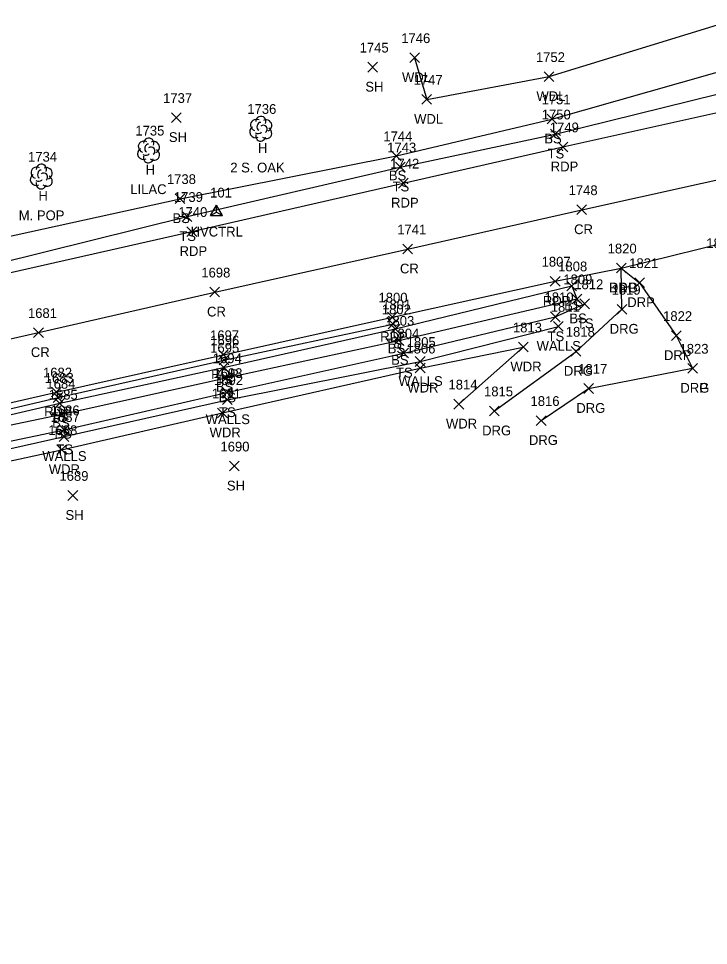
# Model space of a CAD drawing. Extents: x 1611797 to 1633212, y 298978 to 305475.
# Drawn here: x 1613578.2 to 1613719.6, y 301197.3 to 301387.3 of the extents above; entities that cross this region are included whole.
import ezdxf

# ---------------------------------------------------------------- set-up
doc = ezdxf.new("R2010")
doc.units = 0
for name, color, linetype in [('C_A', 7, 'Continuous'), ('C_I', 7, 'Continuous'), ('CPSM', 7, 'Continuous'), ('L_A', 7, 'Continuous'), ('L_C', 7, 'Continuous'), ('L_I', 7, 'Continuous'), ('L_TIC', 7, 'Continuous'), ('LAWA', 7, 'Continuous'), ('LELB', 7, 'Continuous'), ('LTD', 7, 'Continuous'), ('LWS', 7, 'Continuous'), ('P_A', 7, 'Continuous'), ('P_I', 7, 'Continuous'), ('P_TIC', 7, 'Continuous'), ('PET', 7, 'Continuous'), ('PRC', 7, 'Continuous'), ('R_A', 7, 'Continuous'), ('R_I', 7, 'Continuous'), ('R_TIC', 7, 'Continuous'), ('RDG', 7, 'Continuous'), ('RDP', 7, 'Continuous')]:
    doc.layers.add(name, color=color, linetype=linetype)

msp = doc.modelspace()

# ---------------------------------------------------------------- linework, layer by layer
at = {"layer": 'CPSM'}
for p, q in [((1613617.56, 301346.93), (1613618.81, 301349.09)), ((1613617.56, 301346.93), (1613618.81, 301347.65)), ((1613620.06, 301346.93), (1613618.81, 301349.09)), ((1613618.81, 301347.65), (1613618.81, 301349.09)), ((1613618.81, 301347.65), (1613618.81, 301347.65)), ((1613618.81, 301347.65), (1613620.06, 301346.93)), ((1613617.56, 301346.93), (1613620.06, 301346.93))]:
    msp.add_line(p, q, dxfattribs=at)
at = {"layer": 'L_TIC'}
for points in [[(1613658.39, 301378.3), (1613660.39, 301380.3)], [(1613660.39, 301378.3), (1613658.39, 301380.3)], [(1613649.81, 301376.36), (1613651.81, 301378.36)], [(1613651.81, 301376.36), (1613649.81, 301378.36)], [(1613685.93, 301374.42), (1613687.93, 301376.42)], [(1613687.93, 301374.42), (1613685.93, 301376.42)], [(1613660.87, 301369.75), (1613662.87, 301371.75)], [(1613662.87, 301369.75), (1613660.87, 301371.75)], [(1613609.55, 301366.03), (1613611.55, 301368.03)], [(1613611.55, 301366.03), (1613609.55, 301368.03)], [(1613686.53, 301365.74), (1613688.53, 301367.74)], [(1613688.53, 301365.74), (1613686.53, 301367.74)], [(1613687.22, 301362.65), (1613689.22, 301364.65)], [(1613689.22, 301362.65), (1613687.22, 301364.65)], [(1613654.67, 301358.18), (1613656.67, 301360.18)], [(1613656.67, 301358.18), (1613654.67, 301360.18)], [(1613655.46, 301355.9), (1613657.46, 301357.9)], [(1613657.46, 301355.9), (1613655.46, 301357.9)], [(1613610.33, 301349.41), (1613612.33, 301351.41)], [(1613612.33, 301349.41), (1613610.33, 301351.41)], [(1613611.77, 301345.75), (1613613.77, 301347.75)], [(1613613.77, 301345.75), (1613611.77, 301347.75)], [(1613690.58, 301331.52), (1613692.58, 301333.52)], [(1613692.58, 301331.52), (1613690.58, 301333.52)], [(1613691.65, 301328.87), (1613693.65, 301330.87)], [(1613693.65, 301328.87), (1613691.65, 301330.87)], [(1613691.65, 301328.87), (1613693.65, 301330.87)], [(1613693.65, 301328.87), (1613691.65, 301330.87)], [(1613693.23, 301327.86), (1613695.23, 301329.86)], [(1613695.23, 301327.86), (1613693.23, 301329.86)], [(1613687.21, 301325.19), (1613689.21, 301327.19)], [(1613689.21, 301325.19), (1613687.21, 301327.19)], [(1613653.96, 301323.72), (1613655.96, 301325.72)], [(1613655.96, 301323.72), (1613653.96, 301325.72)], [(1613687.84, 301323.24), (1613689.84, 301325.24)], [(1613689.84, 301323.24), (1613687.84, 301325.24)], [(1613654.44, 301322.72), (1613656.44, 301324.72)], [(1613656.44, 301322.72), (1613654.44, 301324.72)], [(1613655.14, 301320.37), (1613657.14, 301322.37)], [(1613657.14, 301320.37), (1613655.14, 301322.37)], [(1613656.17, 301317.76), (1613658.17, 301319.76)], [(1613658.17, 301317.76), (1613656.17, 301319.76)], [(1613680.66, 301319), (1613682.66, 301321)], [(1613682.66, 301319), (1613680.66, 301321)], [(1613619.32, 301316.34), (1613621.32, 301318.34)], [(1613621.32, 301316.34), (1613619.32, 301318.34)], [(1613659.53, 301316.03), (1613661.53, 301318.03)], [(1613661.53, 301316.03), (1613659.53, 301318.03)], [(1613619.25, 301314.84), (1613621.25, 301316.84)], [(1613621.25, 301314.84), (1613619.25, 301316.84)], [(1613659.53, 301314.68), (1613661.53, 301316.68)], [(1613661.53, 301314.68), (1613659.53, 301316.68)], [(1613619.79, 301312.69), (1613621.79, 301314.69)], [(1613621.79, 301312.69), (1613619.79, 301314.69)], [(1613619.91, 301309.65), (1613621.91, 301311.65)], [(1613621.91, 301309.65), (1613619.91, 301311.65)], [(1613585.35, 301308.65), (1613587.35, 301310.65)], [(1613587.35, 301308.65), (1613585.35, 301310.65)], [(1613620.04, 301308.2), (1613622.04, 301310.2)], [(1613622.04, 301308.2), (1613620.04, 301310.2)], [(1613585.69, 301307.47), (1613587.69, 301309.47)], [(1613587.69, 301307.47), (1613585.69, 301309.47)], [(1613667.45, 301307.3), (1613669.45, 301309.3)], [(1613669.45, 301307.3), (1613667.45, 301309.3)], [(1613586.16, 301305.24), (1613588.16, 301307.24)], [(1613588.16, 301305.24), (1613586.16, 301307.24)], [(1613619.03, 301305.5), (1613621.03, 301307.5)], [(1613621.03, 301305.5), (1613619.03, 301307.5)], [(1613586.6, 301302.03), (1613588.6, 301304.03)], [(1613588.6, 301302.03), (1613586.6, 301304.03)], [(1613586.58, 301300.66), (1613588.58, 301302.66)], [(1613588.58, 301300.66), (1613586.58, 301302.66)], [(1613586.08, 301297.95), (1613588.08, 301299.95)], [(1613588.08, 301297.95), (1613586.08, 301299.95)], [(1613621.44, 301294.6), (1613623.44, 301296.6)], [(1613623.44, 301294.6), (1613621.44, 301296.6)], [(1613588.37, 301288.58), (1613590.37, 301290.58)], [(1613590.37, 301288.58), (1613588.37, 301290.58)]]:
    msp.add_lwpolyline(points, dxfattribs=at)
at = {"layer": 'LAWA'}
for points in [[(1613659.39, 301379.3), (1613661.87, 301370.75), (1613686.93, 301375.42), (1613730.09, 301388.72), (1613768.03, 301396.97), (1613816.59, 301404.76), (1613861.02, 301415.83), (1613901.25, 301427.67), (1613950.68, 301436.07), (1613982.7, 301436.25), (1614021.38, 301440.86), (1614060.15, 301445.11), (1614098.09, 301453.38), (1614139.15, 301456.54), (1614173, 301459.52), (1614211.23, 301469.75), (1614243.82, 301473.03), (1614282.31, 301479.54), (1614304.52, 301484.61), (1614323.47, 301484.21), (1614343.41, 301488.74), (1614366.06, 301492.98), (1614391.26, 301497.25)], [(1613542.6, 301289.32), (1613587.08, 301298.95), (1613620.03, 301306.5), (1613660.53, 301315.68), (1613681.66, 301320), (1613668.45, 301308.3)]]:
    msp.add_lwpolyline(points, dxfattribs=at)
at = {"layer": 'LELB'}
for points in [[(1613547.64, 301352.14), (1613554.94, 301342.11), (1613572.12, 301341.76), (1613611.33, 301350.41), (1613655.67, 301359.18), (1613687.53, 301366.74), (1613727.39, 301378.05)], [(1613542.94, 301350.02), (1613549.03, 301339.17), (1613554.76, 301335.6), (1613573.69, 301337.05), (1613612.77, 301346.75), (1613656.46, 301356.9), (1613688.22, 301363.65), (1613727.18, 301373.26)], [(1613463.01, 301262.21), (1613459.37, 301279.97), (1613500.95, 301288.36), (1613538.8, 301297.39), (1613586.69, 301308.47), (1613620.25, 301315.84), (1613655.44, 301323.72), (1613691.58, 301332.52), (1613692.65, 301329.87)], [(1613465.06, 301263.06), (1613463.24, 301277.32), (1613501.35, 301286.48), (1613539.01, 301296.17), (1613587.16, 301306.24), (1613620.79, 301313.69), (1613656.14, 301321.37), (1613692.65, 301329.87)], [(1613538.55, 301292.76), (1613587.6, 301303.03), (1613620.91, 301310.65), (1613657.17, 301318.76), (1613688.21, 301326.19), (1613694.23, 301328.86)], [(1613461.59, 301261.05), (1613458.2, 301280.99), (1613461.48, 301280.97), (1613500.66, 301290.09), (1613538.75, 301298.42), (1613586.35, 301309.65), (1613620.32, 301317.34), (1613654.96, 301324.72)]]:
    msp.add_lwpolyline(points, dxfattribs=at)
at = {"layer": 'LTD'}
for p, q in [((1613627.86, 301364.79), (1613627.86, 301364.79)), ((1613627.86, 301364.79), (1613627.86, 301364.79)), ((1613604.86, 301360.35), (1613604.86, 301360.35)), ((1613604.86, 301360.35), (1613604.86, 301360.35)), ((1613582.88, 301355), (1613582.88, 301355)), ((1613582.88, 301355), (1613582.88, 301355))]:
    msp.add_line(p, q, dxfattribs=at)
for centre in [(1613627.9, 301366.23), (1613604.91, 301361.78), (1613582.93, 301356.44)]:
    msp.add_arc(centre, 1.05, 335.5272, 180.9563, dxfattribs=at)
for centre, major_axis, ratio, start_param, end_param in [((1613627.06, 301365.46), (1.21, -0.51), 0.895232, 1.570796, 4.712389), ((1613628.9, 301365.38), (-1.14, -0.48), 0.949671, 1.570796, 4.712389), ((1613626.77, 301364.08), (0.58, -1.04), 0.959034, 3.141593, 6.283185), ((1613627.65, 301365.25), (-0.208, -0.792), 0.645439, 3.141593, 6.283185), ((1613628.36, 301364.63), (-0.5, 0.667), 0.989748, 3.141593, 6.283185), ((1613628.86, 301363.96), (-1.09, 0.79), 0.841452, 1.570796, 4.712389), ((1613627.86, 301363.29), (0.26, 1.06), 0.942809, 1.570796, 4.712389), ((1613627.4, 301364.04), (-0.625, -0.083), 0.423636, 0, 3.141593), ((1613604.07, 301361.01), (1.21, -0.51), 0.895232, 1.570796, 4.712389), ((1613604.65, 301360.8), (-0.208, -0.792), 0.645439, 3.141593, 6.283185), ((1613605.36, 301360.18), (-0.5, 0.667), 0.989748, 3.141593, 6.283185), ((1613605.9, 301360.93), (-1.14, -0.48), 0.949671, 1.570796, 4.712389), ((1613603.78, 301359.64), (0.58, -1.04), 0.959034, 3.141593, 6.283185), ((1613604.86, 301358.85), (0.26, 1.06), 0.942809, 1.570796, 4.712389), ((1613604.4, 301359.6), (-0.625, -0.083), 0.423636, 0, 3.141593), ((1613605.86, 301359.51), (-1.09, 0.79), 0.841452, 1.570796, 4.712389), ((1613581.8, 301354.3), (0.58, -1.04), 0.959034, 3.141593, 6.283185), ((1613582.09, 301355.67), (1.21, -0.51), 0.895232, 1.570796, 4.712389), ((1613582.68, 301355.46), (-0.208, -0.792), 0.645439, 3.141593, 6.283185), ((1613583.38, 301354.84), (-0.5, 0.667), 0.989748, 3.141593, 6.283185), ((1613583.93, 301355.59), (-1.14, -0.48), 0.949671, 1.570796, 4.712389), ((1613582.88, 301353.5), (0.26, 1.06), 0.942809, 1.570796, 4.712389), ((1613582.43, 301354.25), (-0.625, -0.083), 0.423636, 0, 3.141593), ((1613583.88, 301354.17), (-1.09, 0.79), 0.841452, 1.570796, 4.712389)]:
    msp.add_ellipse(centre, major_axis=major_axis, ratio=ratio, start_param=start_param, end_param=end_param, dxfattribs=at)
at = {"layer": 'LWS'}
msp.add_lwpolyline([(1613464.97, 301272.29), (1613505.88, 301281.77), (1613538.96, 301290.74), (1613587.58, 301301.66), (1613621.04, 301309.2), (1613660.53, 301317.03), (1613688.84, 301324.24)], dxfattribs=at)
at = {"layer": 'P_TIC'}
for points in [[(1613688.79, 301360.01), (1613690.79, 301362.01)], [(1613690.79, 301360.01), (1613688.79, 301362.01)], [(1613656.08, 301352.59), (1613658.08, 301354.59)], [(1613658.08, 301352.59), (1613656.08, 301354.59)], [(1613692.64, 301347.14), (1613694.64, 301349.14)], [(1613694.64, 301347.14), (1613692.64, 301349.14)], [(1613612.75, 301342.67), (1613614.75, 301344.67)], [(1613614.75, 301342.67), (1613612.75, 301344.67)], [(1613656.96, 301339.09), (1613658.96, 301341.09)], [(1613658.96, 301339.09), (1613656.96, 301341.09)], [(1613700.72, 301335.19), (1613702.72, 301337.19)], [(1613702.72, 301335.19), (1613700.72, 301337.19)], [(1613687.18, 301332.49), (1613689.18, 301334.49)], [(1613689.18, 301332.49), (1613687.18, 301334.49)], [(1613617.43, 301330.26), (1613619.43, 301332.26)], [(1613619.43, 301330.26), (1613617.43, 301332.26)], [(1613653.85, 301325.13), (1613655.85, 301327.13)], [(1613655.85, 301325.13), (1613653.85, 301327.13)], [(1613581.34, 301321.95), (1613583.34, 301323.95)], [(1613583.34, 301321.95), (1613581.34, 301323.95)], [(1613619.22, 301317.42), (1613621.22, 301319.42)], [(1613621.22, 301317.42), (1613619.22, 301319.42)], [(1613585, 301309.77), (1613587, 301311.77)], [(1613587, 301309.77), (1613585, 301311.77)]]:
    msp.add_lwpolyline(points, dxfattribs=at)
at = {"layer": 'PET'}
for points in [[(1613121.41, 301224.79), (1613160.56, 301237.68), (1613191.83, 301246.9), (1613232.03, 301257.4), (1613266.78, 301265.99), (1613307.07, 301275.59), (1613345.71, 301284.52), (1613390.57, 301294.41), (1613429.34, 301303.04), (1613467.51, 301311.15), (1613505.79, 301320.12), (1613518.1, 301323.19), (1613528.91, 301326.43), (1613552.82, 301331.16), (1613574.84, 301334.87), (1613613.75, 301343.67), (1613657.08, 301353.59), (1613689.79, 301361.01), (1613727.87, 301369.49)], [(1613125.52, 301197.34), (1613165.46, 301210.56), (1613197.64, 301220.33), (1613235.96, 301230.65), (1613275.93, 301240.9), (1613310.52, 301248.77), (1613348.15, 301257.49), (1613383.51, 301265), (1613415.7, 301272.42), (1613432.15, 301275.92), (1613434.22, 301275.29), (1613458.2, 301280.99), (1613500.19, 301291.63), (1613538.86, 301299.99), (1613586, 301310.77), (1613620.22, 301318.42), (1613654.85, 301326.13), (1613688.18, 301333.49), (1613701.72, 301336.19), (1613728.29, 301342.74)]]:
    msp.add_lwpolyline(points, dxfattribs=at)
at = {"layer": 'PRC'}
msp.add_lwpolyline([(1613120.36, 301208.99), (1613162.25, 301223.48), (1613195.66, 301233.48), (1613234.87, 301243.9), (1613270.14, 301252.64), (1613310.48, 301262.07), (1613348.55, 301270.95), (1613393.4, 301280.86), (1613432.68, 301289.65), (1613457.43, 301294.66), (1613497.12, 301303.83), (1613537.55, 301312.86), (1613582.34, 301322.95), (1613618.43, 301331.26), (1613657.96, 301340.09), (1613693.64, 301348.14), (1613730.35, 301356.23)], dxfattribs=at)
at = {"layer": 'R_TIC'}
for points in [[(1613700.72, 301335.19), (1613702.72, 301337.19)], [(1613702.72, 301335.19), (1613700.72, 301337.19)], [(1613700.72, 301335.19), (1613702.72, 301337.19)], [(1613702.72, 301335.19), (1613700.72, 301337.19)], [(1613704.48, 301332.19), (1613706.48, 301334.19)], [(1613706.48, 301332.19), (1613704.48, 301334.19)], [(1613700.87, 301326.74), (1613702.87, 301328.74)], [(1613702.87, 301326.74), (1613700.87, 301328.74)], [(1613712, 301321.34), (1613714, 301323.34)], [(1613714, 301321.34), (1613712, 301323.34)], [(1613691.48, 301318.12), (1613693.48, 301320.12)], [(1613693.48, 301318.12), (1613691.48, 301320.12)], [(1613715.35, 301314.64), (1613717.35, 301316.64)], [(1613717.35, 301314.64), (1613715.35, 301316.64)], [(1613715.35, 301314.64), (1613717.35, 301316.64)], [(1613717.35, 301314.64), (1613715.35, 301316.64)], [(1613694.03, 301310.51), (1613696.03, 301312.51)], [(1613696.03, 301310.51), (1613694.03, 301312.51)], [(1613674.74, 301305.9), (1613676.74, 301307.9)], [(1613676.74, 301305.9), (1613674.74, 301307.9)], [(1613684.32, 301303.93), (1613686.32, 301305.93)], [(1613686.32, 301303.93), (1613684.32, 301305.93)]]:
    msp.add_lwpolyline(points, dxfattribs=at)
at = {"layer": 'RDG'}
for points in [[(1613675.74, 301306.9), (1613692.48, 301319.12), (1613701.87, 301327.74), (1613701.72, 301336.19)], [(1613685.32, 301304.93), (1613695.03, 301311.51), (1613716.35, 301315.64)]]:
    msp.add_lwpolyline(points, dxfattribs=at)
at = {"layer": 'RDP'}
msp.add_lwpolyline([(1613701.72, 301336.19), (1613705.48, 301333.19), (1613713, 301322.34), (1613716.35, 301315.64)], dxfattribs=at)

# ---------------------------------------------------------------- texts
at = {"layer": 'C_A'}
msp.add_text('HVCTRL', height=2, dxfattribs=at).set_placement((1613613.5, 301342.65))
at = {"layer": 'C_I'}
msp.add_text('101', height=2, dxfattribs=at).set_placement((1613617.5, 301350.65))
at = {"layer": 'L_A'}
for s, p in [('WDL', (1613656.81, 301374.3)), ('SH', (1613649.3, 301372.36)), ('WDL', (1613684.35, 301370.42)), ('WDL', (1613659.29, 301365.75)), ('SH', (1613609.04, 301362.03)), ('BS', (1613685.97, 301361.74)), ('H', (1613627.29, 301359.79)), ('TS', (1613686.63, 301358.65)), ('H', (1613604.29, 301355.35)), ('BS', (1613654.11, 301354.18)), ('TS', (1613654.87, 301351.9)), ('H', (1613582.32, 301350)), ('BS', (1613609.78, 301345.41)), ('TS', (1613611.18, 301341.75)), ('BS', (1613690.02, 301327.52)), ('BS', (1613691.09, 301324.87)), ('BS', (1613691.09, 301324.87)), ('TS', (1613692.64, 301323.86)), ('TS', (1613686.62, 301321.19)), ('TS', (1613653.37, 301319.72)), ('WALLS', (1613684.39, 301319.24)), ('BS', (1613653.89, 301318.72)), ('BS', (1613654.58, 301316.37)), ('TS', (1613655.58, 301313.76)), ('WDR', (1613679.02, 301315)), ('TS', (1613618.73, 301312.34)), ('WALLS', (1613656.08, 301312.03)), ('BS', (1613618.69, 301310.84)), ('WDR', (1613657.9, 301310.68)), ('BS', (1613619.23, 301308.69)), ('TS', (1613584.76, 301304.65)), ('WALLS', (1613616.59, 301304.2)), ('TS', (1613619.32, 301305.65)), ('BS', (1613585.14, 301303.47)), ('WDR', (1613665.82, 301303.3)), ('BS', (1613585.6, 301301.24)), ('WDR', (1613617.39, 301301.5)), ('WALLS', (1613583.12, 301296.66)), ('TS', (1613586.01, 301298.03)), ('WDR', (1613584.44, 301293.95)), ('SH', (1613620.93, 301290.6)), ('SH', (1613587.86, 301284.58))]:
    msp.add_text(s, height=2, dxfattribs=at).set_placement(p)
at = {"layer": 'L_C'}
for s, p in [('2 S. OAK', (1613621.62, 301355.79)), ('LILAC', (1613601.14, 301351.35)), ('M. POP', (1613578.29, 301346))]:
    msp.add_text(s, height=2, dxfattribs=at).set_placement(p)
at = {"layer": 'L_I'}
for s, p in [('1746', (1613656.65, 301382.3)), ('1745', (1613648.12, 301380.36)), ('1752', (1613684.24, 301378.42)), ('1747', (1613659.18, 301373.75)), ('1737', (1613607.86, 301370.03)), ('1751', (1613685.4, 301369.74)), ('1736', (1613625.11, 301367.79)), ('1750', (1613685.44, 301366.65)), ('1735', (1613602.17, 301363.35)), ('1744', (1613652.98, 301362.18)), ('1743', (1613653.77, 301359.9)), ('1734', (1613580.19, 301358)), ('1738', (1613608.64, 301353.41)), ('1739', (1613610.07, 301349.75)), ('1808', (1613688.81, 301335.52)), ('1809', (1613689.87, 301332.87)), ('1809', (1613689.87, 301332.87)), ('1812', (1613692.1, 301331.86)), ('1810', (1613686, 301329.19)), ('1802', (1613652.67, 301326.72)), ('1801', (1613652.76, 301327.72)), ('1811', (1613687.29, 301327.24)), ('1803', (1613653.37, 301324.37)), ('1813', (1613679.53, 301323)), ('1804', (1613654.4, 301321.76)), ('1696', (1613617.52, 301320.34)), ('1805', (1613657.76, 301320.03)), ('1695', (1613617.51, 301318.84)), ('1806', (1613657.71, 301318.68)), ('1694', (1613618.05, 301316.69)), ('1693', (1613618.17, 301313.65)), ('1683', (1613583.61, 301312.65)), ('1684', (1613583.95, 301311.47)), ('1692', (1613618.3, 301312.2)), ('1691', (1613617.86, 301309.5)), ('1814', (1613666.33, 301311.3)), ('1685', (1613584.42, 301309.24)), ('1686', (1613584.81, 301306.03)), ('1687', (1613584.84, 301304.66)), ('1688', (1613584.34, 301301.95)), ('1690', (1613619.61, 301298.6)), ('1689', (1613586.62, 301292.58))]:
    msp.add_text(s, height=2, dxfattribs=at).set_placement(p)
at = {"layer": 'P_A'}
for s, p in [('RDP', (1613687.28, 301356.01)), ('RDP', (1613654.57, 301348.59)), ('CR', (1613692.07, 301343.14)), ('RDP', (1613611.24, 301338.67)), ('CR', (1613656.39, 301335.09)), ('RDP', (1613699.21, 301331.19)), ('RDP', (1613685.67, 301328.49)), ('CR', (1613616.86, 301326.26)), ('RDP', (1613652.34, 301321.13)), ('CR', (1613580.77, 301317.95)), ('RDP', (1613617.71, 301313.42)), ('RDP', (1613583.49, 301305.77))]:
    msp.add_text(s, height=2, dxfattribs=at).set_placement(p)
at = {"layer": 'P_I'}
for s, p in [('1749', (1613687.09, 301364.01)), ('1742', (1613654.39, 301356.59)), ('1748', (1613690.94, 301351.14)), ('1740', (1613610.97, 301346.67)), ('1741', (1613655.83, 301343.09)), ('1820', (1613698.94, 301339.19)), ('1807', (1613685.41, 301336.49)), ('1698', (1613615.69, 301334.26)), ('1800', (1613651.99, 301329.13)), ('1681', (1613580.17, 301325.95)), ('1697', (1613617.48, 301321.42)), ('1682', (1613583.26, 301313.77))]:
    msp.add_text(s, height=2, dxfattribs=at).set_placement(p)
at = {"layer": 'R_A'}
for s, p in [('DRG', (1613699.21, 301331.19)), ('DRP', (1613699.21, 301331.19)), ('DRP', (1613702.96, 301328.19)), ('DRG', (1613699.36, 301322.74)), ('DRP', (1613710.48, 301317.34)), ('DRG', (1613689.97, 301314.12)), ('DRG', (1613713.84, 301310.64)), ('DRP', (1613713.84, 301310.64)), ('DRG', (1613692.52, 301306.51)), ('DRG', (1613673.22, 301301.9)), ('DRG', (1613682.81, 301299.93))]:
    msp.add_text(s, height=2, dxfattribs=at).set_placement(p)
at = {"layer": 'R_I'}
for s, p in [('1826', (1613719.14, 301340.28)), ('1826', (1613719.14, 301340.28)), ('1820', (1613698.94, 301339.19)), ('1820', (1613698.94, 301339.19)), ('1821', (1613703.35, 301336.19)), ('1819', (1613699.74, 301330.74)), ('1822', (1613710.3, 301325.34)), ('1818', (1613690.36, 301322.12)), ('1823', (1613713.66, 301318.64)), ('1823', (1613713.66, 301318.64)), ('1817', (1613692.91, 301314.51)), ('1815', (1613673.61, 301309.9)), ('1816', (1613683.14, 301307.93))]:
    msp.add_text(s, height=2, dxfattribs=at).set_placement(p)

doc.saveas('drawing.dxf')
